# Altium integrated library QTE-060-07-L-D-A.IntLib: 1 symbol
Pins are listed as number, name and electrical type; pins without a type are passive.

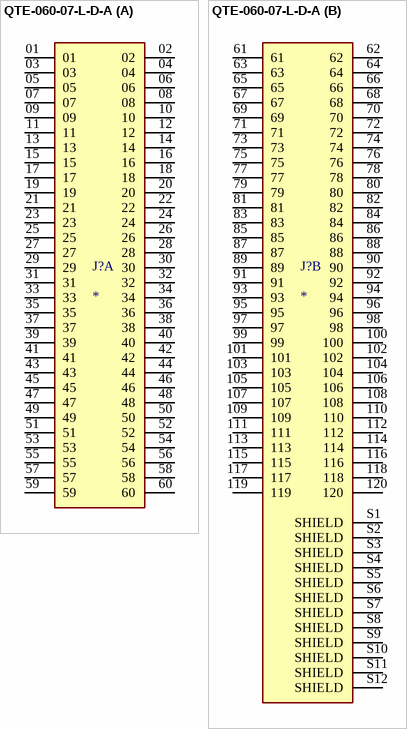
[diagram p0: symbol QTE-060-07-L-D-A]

## QTE-060-07-L-D-A
designator J?
120 Position Connector Header, Outer Shroud Contacts Surface Mount Gold   <a href="https://pricing.snapeda.com/parts/QTE-060-01-H-D-A/Samtec/view-part?ref=eda">Check availability</a> <a href="https://pricing.snapeda.com/parts/QTE-060-01-H-D-A/Samtec/view-part?ref=eda">Check availability</a>; MF: Samtec; MP: QTE-060-07-L-D-A
footprint SAMTEC_QTE-060-07-L-D-A
part A pins: 01, 02, 03, 04, 05, 06, 07, 08, 09, 10, 11, 12, 13, 14, 15, 16, 17, 18, 19, 20, 21, 22, 23, 24, 25, 26, 27, 28, 29, 30, 31, 32, 33, 34, 35, 36, 37, 38, 39, 40, 41, 42, 43, 44, 45, 46, 47, 48, 49, 50, 51, 52, 53, 54, 55, 56, 57, 58, 59, 60
part B pins: 61, 62, 63, 64, 65, 66, 67, 68, 69, 70, 71, 72, 73, 74, 75, 76, 77, 78, 79, 80, 81, 82, 83, 84, 85, 86, 87, 88, 89, 90, 91, 92, 93, 94, 95, 96, 97, 98, 99, 100, 101, 102, 103, 104, 105, 106, 107, 108, 109, 110, 111, 112, 113, 114, 115, 116, 117, 118, 119, 120, S1 SHIELD, S2 SHIELD, S3 SHIELD, S4 SHIELD, S5 SHIELD, S6 SHIELD, S7 SHIELD, S8 SHIELD, S9 SHIELD, S10 SHIELD, S11 SHIELD, S12 SHIELD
